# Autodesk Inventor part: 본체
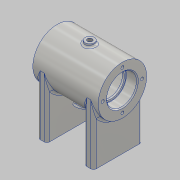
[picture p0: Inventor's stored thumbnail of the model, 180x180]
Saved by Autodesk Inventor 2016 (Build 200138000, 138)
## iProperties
Created: 2020-07
Part Number: 본체
Material: 알루미늄 6061
Document SubType Name: Modeling
Designer: 605-11
Mass: 305.247 g
Surface Area: 357.577 cm^2
Volume: 113.055 cm^3
Density: 2.7 g/cm^3
Appearance: 알루미늄 - 평지
Author: 605-11
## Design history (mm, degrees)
sketch "스케치1"
  geometry: L1 (-35, 0)-(35, 0); L2 (-35, 0)-(-35, 26); L3 (-35, 26)-(35, 26); L4 (35, 26)-(35, 0); L5 (-35, 16)-(-23, 16); L6 (-23, 16)-(-23, 14); L7 (-23, 14)-(-21, 14); L8 (-21, 14)-(-21, 21); L9 (-21, 21)-(21, 21); L10 (21, 21)-(21, 14); L11 (21, 14)-(23, 14); L12 (23, 14)-(23, 16); L13 (23, 16)-(35, 16); 2 further points
  constraints: 26 end point, 8 perpendicular, 3 horizontal, 2 point on line, 2 vertical, 1 coincident, 1 midpoint
  dimensions: "d0" = 12 distance between parallel lines of L2 L6; "d1" = 12 distance between parallel lines of L4 L12; "d2" = 2 distance between parallel lines of L6 L8; "d3" = 2 distance between parallel lines of L10 L12; "d4" = 70 distance of L1.start L1.end; "d5" = 32 diameter of L5 L1; "d6" = 28 diameter of L7 L1; "d7" = 42 diameter of L9 L1; "d8" = 28 diameter of L11 L1; "d9" = 32 diameter of L13 L1; "d10" = 52 diameter of L3 L1
revolve "회전1" sketch "스케치1" stored, may be unused: angle "d11" = 90 deg
sketch "스케치2" dims "d12" = 42
  geometry: L1 (0, 0)-(-21, 0); 1 further point
  constraints: 2 end point, 1 coincident, 1 horizontal, 1 horizontal alignment, 2 other
hole "구멍1" sketch "스케치2" at (-21, 0) diameter "d13" = 3.242; stored, may be unused: countersink angle "d17" = 90 deg, drill point angle "d19" = 118 deg; dims "d14" = 8, "d15" = 4, "d16" = 2, "d18" = 10
node "작업 평면1"
sketch "스케치3"
  geometry: C1 r 5 at (0, 0); 1 further point
  constraints: 1 centre point, 1 coincident
  dimensions: "d24" = 10 diameter of C1
extrude "돌출1" join sketch "스케치3" stored distance "d25" = 10; taper "d26" = 0 deg
hole "구멍2" diameter "d29" = 5.188; stored, may be unused: countersink angle "d33" = 90 deg, drill point angle "d35" = 118 deg; dims "d27" = 10, "d28" = 10, "d30" = 12, "d31" = 4, "d32" = 2, "d34" = 16
sketch "스케치4"
  geometry: L1 (0, 0)-(-9.919, -27.251); L2 (0, 0)-(0, -19.125); C1 r 21 at (0, 0) reference; 1 further point
  constraints: 4 end point, 1 vertical
  dimensions: "d36" = 20 deg angle of L2 L1; "d37" = 29 distance of L1.start L1.end
node "작업 평면3"
sketch "스케치5"
  geometry: L1 (-30, -26)-(-20, -26); L2 (-20, -26)-(-20, 26); L3 (-20, 26)-(-30, 26); L4 (-30, 26)-(-30, -26); L5 (30, 26)-(20, 26); L6 (20, 26)-(20, -26); L7 (20, -26)-(30, -26); L8 (30, -26)-(30, 26); 3 further points
  constraints: 16 end point, 4 parallel, 2 horizontal, 2 horizontal alignment, 2 midpoint, 2 perpendicular
  dimensions: "d39" = 10 distance of L2.end L3.end; "d40" = 20 distance from line of point (0, 0) L2; "d41" = 52 distance of L3.end L1.start; "d42" = 10 distance of L5.start L5.end; "d43" = 52 distance of L7.end L5.start; "d44" = 20 distance from line of point (0, 0) L6
extrude "돌출2" join sketch "스케치5" stored distance "d45" = 10; taper "d46" = 0 deg
sketch "스케치6"
  geometry: L1 (-30, -26)-(-30, 26) reference; 3 further points
  dimensions: "d47" = 5 distance from line of L1 point (-25, -20); "d48" = 20 vertical distance of point (-25, -20) point (0, 0); "d49" = 20 vertical distance of point (-25, 20) point (0, 0); "d50" = 5 distance from line of L1 point (-25, 20)
hole "구멍3" sketch "스케치6" at (-25, -20), (-25, 20) diameter "d51" = 4.134; stored, may be unused: countersink angle "d55" = 90 deg, drill point angle "d57" = 118 deg; dims "d52" = 8, "d53" = 4, "d54" = 2, "d56" = 10
sketch "스케치7"
  geometry: L1 (30, 26)-(30, -26) reference; 3 further points
  dimensions: "d58" = 5 distance from line of L1 point (25, 20); "d59" = 20 vertical distance of point (25, 20) point (0, 0); "d60" = 20 vertical distance of point (0, 0) point (25, -20); "d61" = 5 distance from line of point (25, -20) L1
hole "구멍4" sketch "스케치7" at (25, 20), (25, -20) diameter "d62" = 4.134; stored, may be unused: countersink angle "d66" = 90 deg, drill point angle "d68" = 118 deg; dims "d63" = 8, "d64" = 4, "d65" = 2, "d67" = 10
node "작업 평면6"
sketch "스케치8"
  geometry: C1 r 6 at (0, 0); 1 further point
  constraints: 1 centre point, 1 coincident
  dimensions: "d69" = 12 diameter of C1
extrude "돌출3" join sketch "스케치8" stored distance "d70" = 10; taper "d71" = 0 deg
hole "구멍5" diameter "d74" = 5.188; stored, may be unused: countersink angle "d78" = 90 deg, drill point angle "d80" = 118 deg; dims "d72" = 10, "d73" = 10, "d75" = 12, "d76" = 4, "d77" = 2, "d79" = 16
fillet "모깎기1" dims "d81" = 2
fillet "모깎기2" dims "d82" = 3
fillet "모깎기3" dims "d83" = 3
fillet "모깎기4" dims "d84" = 3
chamfer "모따기1" distance "d85" = 1; stored, may be unused: second distance "d86" = 2, angle "d87" = 45 deg
fillet "모깎기5" dims "d88" = 0.3
node "작업 평면7"
sketch "스케치9"
  geometry: L1 (-13.563, 4.296)-(13.563, 4.296); L2 (13.563, 4.296)-(13.563, -4.296); L3 (13.563, -4.296)-(-13.563, -4.296); L4 (-13.563, -4.296)-(-13.563, 4.296); L5 (-13.563, 0)-(13.563, 0); L6 (0, 4.296)-(0, -4.296); L7 (-35, 26)-(-35, -26) reference; L8 (35, 26)-(-35, 26) reference; 1 further point
  constraints: 4 end point, 4 midpoint, 2 other
  dimensions: "d89" = 35 distance between parallel lines of L7 L6; "d90" = 26 distance between parallel lines of L5 L8
feature "엠보싱1" sketch "스케치9" dims "d0" = 12, "d1" = 12, "d2" = 2, "d3" = 2, "d4" = 70, "d5" = 32, "d6" = 28, "d7" = 42, "d8" = 28, "d9" = 32, "d10" = 52, "d91" = 0.5, "d92" = 0
node "솔리드1"
pattern_circular "원형 패턴1" dims angle "d21" = 360 deg
mirror "대칭1"
other parameters: "d23" = 29, "d38" = -64
